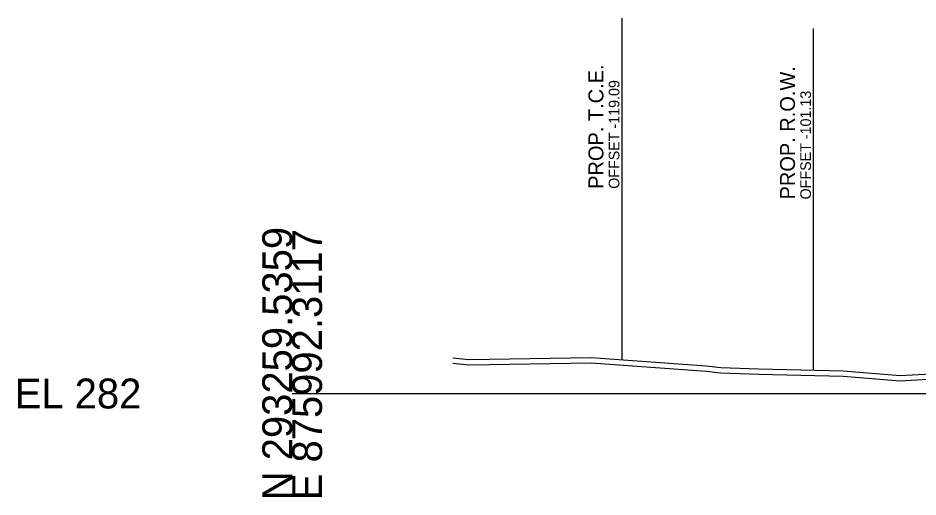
# Model space of a CAD drawing. Extents: x -26 to 875706, y -30 to 290725.
# Drawn here: x 1974.3 to 2058.6, y 4490.3 to 4535.2 of the extents above; entities that cross this region are included whole.
import ezdxf

# ---------------------------------------------------------------- set-up
doc = ezdxf.new("R2010")
doc.units = 0
for name, color, linetype in [('DESIGN - ROW - Easement Linework and Patterning', 7, 'Continuous'), ('DESIGN - ROW - Right-of-Way and Easement Labels', 7, 'Continuous'), ('DESIGN - ROW - Right-of-Way Linework', 7, 'Continuous'), ('DESIGN - SHEET - Light Grid', 7, 'Continuous'), ('SURVEY - GROUND - Bottom of Topsoil Layer', 7, 'Continuous'), ('SURVEY - GROUND - Top of Ground', 7, 'Continuous')]:
    doc.layers.add(name, color=color, linetype=linetype)

msp = doc.modelspace()

# ---------------------------------------------------------------- linework, layer by layer
at = {"layer": 'DESIGN - ROW - Easement Linework and Patterning'}
msp.add_line((2030.912, 4503.176), (2030.912, 4535.176), dxfattribs=at)
at = {"layer": 'DESIGN - ROW - Right-of-Way Linework'}
msp.add_line((2048.865, 4502.18), (2048.865, 4534.18), dxfattribs=at)
at = {"layer": 'DESIGN - SHEET - Light Grid'}
msp.add_line((2000, 4500), (2150, 4500), dxfattribs=at)
at = {"layer": 'SURVEY - GROUND - Bottom of Topsoil Layer'}
for p, q in [((2015.043, 4502.835), (2016.565, 4502.688)), ((2016.565, 4502.688), (2028.025, 4502.889)), ((2028.025, 4502.889), (2038.805, 4502.093)), ((2038.805, 4502.093), (2040.182, 4501.932)), ((2040.182, 4501.932), (2043.71, 4501.8)), ((2043.71, 4501.8), (2051.642, 4501.616)), ((2051.642, 4501.616), (2056.976, 4501.196)), ((2056.976, 4501.196), (2062.123, 4501.478))]:
    msp.add_line(p, q, dxfattribs=at)
at = {"layer": 'SURVEY - GROUND - Top of Ground'}
msp.add_lwpolyline([(2015.043, 4503.335), (2016.565, 4503.188), (2028.025, 4503.389), (2038.805, 4502.593), (2040.182, 4502.432), (2043.71, 4502.3), (2051.642, 4502.116), (2056.976, 4501.696), (2062.123, 4501.978)], dxfattribs=at)

# ---------------------------------------------------------------- texts
at = {"layer": 'DESIGN - ROW - Right-of-Way and Easement Labels'}
for s, height, p in [('PROP. T.C.E.', 1.4, (2029.162, 4519.176)), ('PROP. R.O.W.', 1.4, (2047.115, 4518.18)), ('OFFSET -119.09', 1, (2030.662, 4519.176)), ('OFFSET -101.13', 1, (2048.615, 4518.18))]:
    msp.add_text(s, height=height, rotation=90, dxfattribs=at).set_placement(p)
at = {"layer": 'DESIGN - SHEET - Light Grid'}
for s, p in [('N 293259.5359', (2000, 4490)), ('E 875992.3117', (2002.8, 4490))]:
    msp.add_text(s, height=2.8, rotation=90, dxfattribs=at).set_placement(p)
msp.add_text('EL 282', height=2.8, dxfattribs=at).set_placement((1974, 4498.6))

doc.saveas('drawing.dxf')
